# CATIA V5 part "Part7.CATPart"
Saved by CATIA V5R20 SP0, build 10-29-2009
Part number: Part7
Bounding box of the stored display mesh (mm): x 0 to 20, y 48.284 to 48.284, z 73.126 to 73.126
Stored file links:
  C:\Documents and Settings\Media\Escritorio\GATO_ALAMBRICO\Part7.CATPart
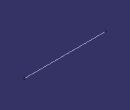
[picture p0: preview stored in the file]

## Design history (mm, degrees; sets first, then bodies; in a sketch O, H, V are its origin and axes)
Set1
  Line1: type PtDir, RefPoint DatumPoint1, Direction yz-plane, Start 0, End 20
  DatumPoint1
Body1 (main body)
